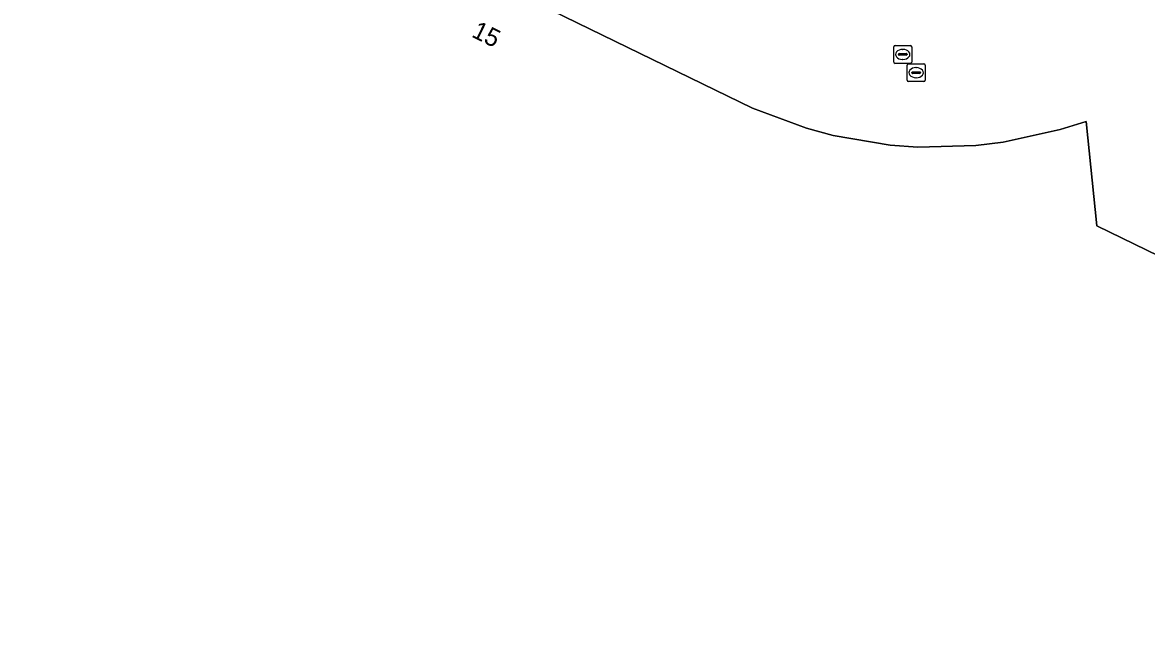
# Model space of a CAD drawing. Extents: x 156141 to 158132, y 385651 to 388333.
# Drawn here: x 156555.8 to 156618.4, y 386572.8 to 386606.3 of the extents above; entities that cross this region are included whole.
import ezdxf

# ---------------------------------------------------------------- set-up
doc = ezdxf.new("R2010")
doc.units = 0
for name, color, linetype in [('IMGEO_Erf', 7, 'Continuous'), ('IMGEO_Pand', 7, 'Continuous'), ('IMGEO_Pand_nummerreeks', 7, 'Continuous'), ('IMGEO_Rioolput', 7, 'Continuous')]:
    doc.layers.add(name, color=color, linetype=linetype)

msp = doc.modelspace()

# ---------------------------------------------------------------- linework, layer by layer
at = {"layer": 'IMGEO_Erf'}
msp.add_lwpolyline([(156500, 386548.209), (156536.341, 386622.805), (156566.089, 386608.323), (156569.213, 386614.732), (156596.408, 386601.474), (156599.425, 386600.358), (156600.911, 386599.949), (156604.086, 386599.42), (156605.629, 386599.31), (156608.85, 386599.398), (156610.375, 386599.588), (156613.543, 386600.283), (156614.995, 386600.738), (156615.595, 386594.927), (156637.747, 386584.139), (156633.6, 386575.406), (156698.58, 386543.772)], dxfattribs=at)
at = {"layer": 'IMGEO_Pand'}
msp.add_lwpolyline([(156698.58, 386543.772), (156633.6, 386575.406), (156637.747, 386584.139), (156615.595, 386594.927), (156614.995, 386600.738), (156613.543, 386600.283), (156610.375, 386599.588), (156608.85, 386599.398), (156605.629, 386599.31), (156604.086, 386599.42), (156600.911, 386599.949), (156599.425, 386600.358), (156596.408, 386601.474), (156569.213, 386614.732), (156566.089, 386608.323), (156536.341, 386622.805), (156500, 386548.209)], dxfattribs=at)
at = {"layer": 'IMGEO_Rioolput'}
for p, q in [((156604.278, 386604.048), (156604.278, 386604.9)), ((156604.353, 386604.974), (156605.205, 386604.974)), ((156604.537, 386604.468), (156604.537, 386604.48)), ((156604.975, 386604.431), (156604.577, 386604.431)), ((156604.58, 386604.517), (156604.978, 386604.517)), ((156604.766, 386604.754), (156604.791, 386604.754)), ((156605.021, 386604.48), (156605.021, 386604.468)), ((156605.279, 386604.9), (156605.279, 386604.048)), ((156605.205, 386603.974), (156604.353, 386603.974)), ((156604.789, 386604.194), (156604.764, 386604.194)), ((156605.026, 386603.03), (156605.026, 386603.882)), ((156605.101, 386603.956), (156605.953, 386603.956)), ((156606.027, 386603.882), (156606.027, 386603.03)), ((156605.285, 386603.45), (156605.285, 386603.462)), ((156605.723, 386603.413), (156605.325, 386603.413)), ((156605.328, 386603.499), (156605.726, 386603.499)), ((156605.537, 386603.176), (156605.512, 386603.176)), ((156605.514, 386603.736), (156605.539, 386603.736)), ((156605.769, 386603.462), (156605.769, 386603.45)), ((156605.953, 386602.956), (156605.101, 386602.956))]:
    msp.add_line(p, q, dxfattribs=at)
for points in [[(156604.278, 386604.048), (156604.278, 386604.9)], [(156604.353, 386604.974), (156605.205, 386604.974)], [(156605.279, 386604.9), (156605.279, 386604.048)], [(156605.205, 386603.974), (156604.353, 386603.974)], [(156605.026, 386603.03), (156605.026, 386603.882)], [(156605.101, 386603.956), (156605.953, 386603.956)], [(156606.027, 386603.882), (156606.027, 386603.03)], [(156605.953, 386602.956), (156605.101, 386602.956)]]:
    msp.add_lwpolyline(points, dxfattribs=at)
for centre, radius, start, end in [((156604.355, 386604.898), 0.0765, 91.55205, 178.44795), ((156604.355, 386604.898), 0.0765, 91.55205, 178.44795), ((156604.577, 386604.477), 0.0403, 85.87752, 175.75265), ((156604.574, 386604.467), 0.0366, 178.93798, 274.71019), ((156604.978, 386604.474), 0.043, 264.86636, 352.45326), ((156604.982, 386604.479), 0.0386, 1.73085, 96.63898), ((156605.203, 386604.898), 0.0765, 1.55205, 88.44795), ((156605.203, 386604.898), 0.0765, 1.55205, 88.44795), ((156604.355, 386604.05), 0.0765, 181.55205, 268.44795), ((156604.355, 386604.05), 0.0765, 181.55205, 268.44795), ((156605.103, 386603.88), 0.0765, 91.55205, 178.44795), ((156605.103, 386603.88), 0.0765, 91.55205, 178.44795), ((156605.203, 386604.05), 0.0765, 271.55205, 358.44795), ((156605.203, 386604.05), 0.0765, 271.55205, 358.44795), ((156605.951, 386603.88), 0.0765, 1.55205, 88.44795), ((156605.951, 386603.88), 0.0765, 1.55205, 88.44795), ((156605.325, 386603.459), 0.0403, 85.87752, 175.75265), ((156605.322, 386603.449), 0.0366, 178.93798, 274.71019), ((156605.726, 386603.456), 0.043, 264.86636, 352.45326), ((156605.73, 386603.461), 0.0386, 1.73085, 96.63898), ((156605.103, 386603.032), 0.0765, 181.55205, 268.44795), ((156605.103, 386603.032), 0.0765, 181.55205, 268.44795), ((156605.951, 386603.032), 0.0765, 271.55205, 358.44795), ((156605.951, 386603.032), 0.0765, 271.55205, 358.44795)]:
    msp.add_arc(centre, radius, start, end, dxfattribs=at)
for centre, major_axis, ratio, start_param, end_param in [((156604.765, 386604.474), (-0.387, 0.002), 0.722429, 4.712389, 7.853982), ((156604.79, 386604.474), (-0.39, 0.002), 0.717154, 1.570796, 4.712389), ((156605.513, 386603.456), (-0.387, 0.002), 0.722429, 4.712389, 7.853982), ((156605.538, 386603.456), (-0.39, 0.002), 0.717154, 1.570796, 4.712389)]:
    msp.add_ellipse(centre, major_axis=major_axis, ratio=ratio, start_param=start_param, end_param=end_param, dxfattribs=at)

# ---------------------------------------------------------------- texts
at = {"layer": 'IMGEO_Pand_nummerreeks'}
msp.add_text('15', height=1, rotation=334.01063, dxfattribs=at).set_placement((156580.715, 386605.476))

doc.saveas('drawing.dxf')
